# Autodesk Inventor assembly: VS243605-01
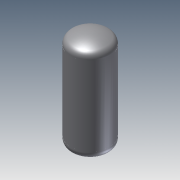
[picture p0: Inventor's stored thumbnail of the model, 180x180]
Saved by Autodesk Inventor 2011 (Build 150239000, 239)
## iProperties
Created: 2010-06
Part Number: VS243605-01
Document SubType Name: Assembly
Designer: mklassen
OD: 36.000 in
THK: 0.625 in
LEN: 6.000 ft
Author: mklassen
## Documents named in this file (3)
- O:\cadd\tutorials\inventor 2011\iLogic\VS243605-01.iam
- O:\cadd\tutorials\inventor 2011\iLogic\Shell-02.ipt
- O:\cadd\tutorials\inventor 2011\iLogic\Head-02.ipt
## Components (3 placed, 2 different names)
1. Shell-02:1 — Mate:2
2. Head-02:1
3. Head-02:2
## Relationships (1: Mate 1)
- Mate:2: Shell-02:1
## Named parameters: SKOFS = -152.4 mm
